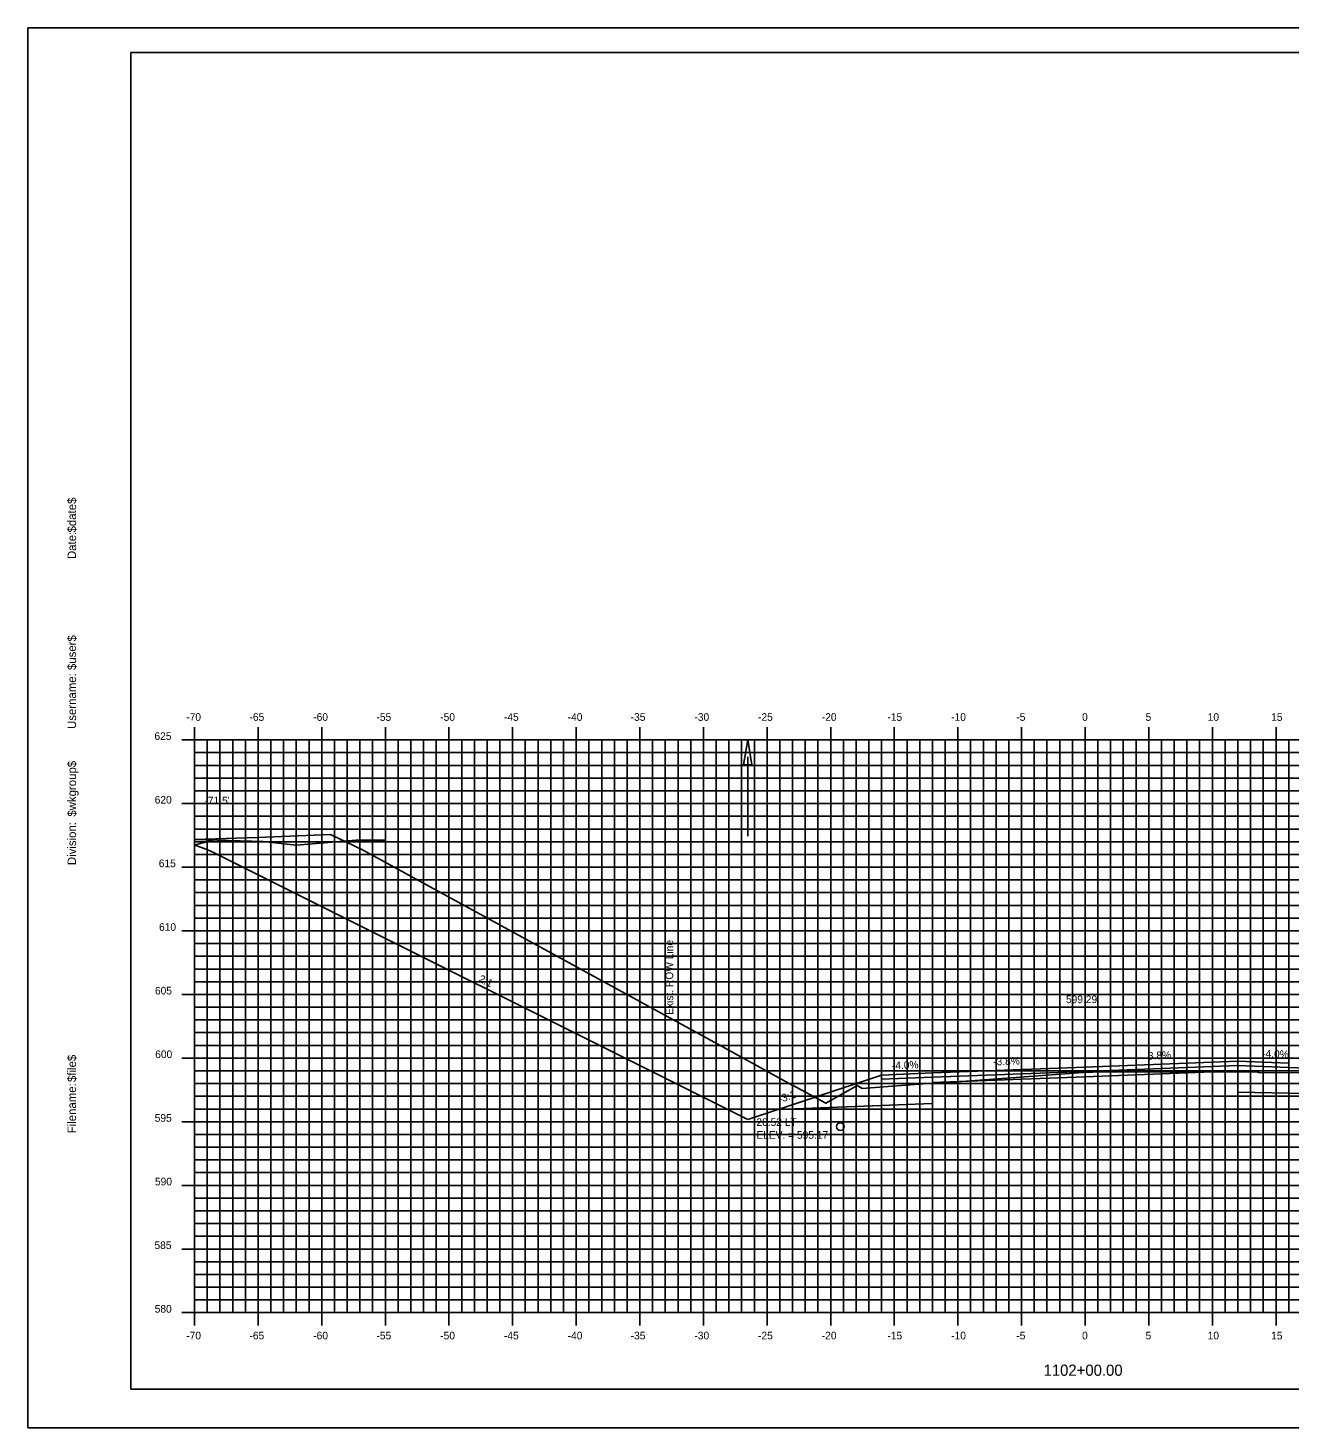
# Model space of a CAD drawing. Extents: x 1076969 to 1077139, y 779716 to 779826.
# Drawn here: x 1076969 to 1077068.1, y 779715.6 to 779825.6 of the extents above; entities that cross this region are included whole.
import ezdxf

# ---------------------------------------------------------------- set-up
doc = ezdxf.new("R2010")
doc.units = 0
for name, color, linetype in [('ANNOTATION', 7, 'Continuous'), ('BORDER', 7, 'Continuous'), ('D_Drainage_Ditch_Line', 7, 'Continuous'), ('D_Roadway_Centerline', 7, 'Continuous'), ('D_Roadway_Centerline_Text', 7, 'Continuous'), ('D_Roadway_Drive_Gravel_LT', 7, 'Continuous'), ('D_Roadway_Drive_SubGrade', 7, 'Continuous'), ('D_Roadway_Edge_Pavement', 7, 'Continuous'), ('D_Roadway_Edge_Shoulder', 7, 'Continuous'), ('D_Roadway_Pavement', 7, 'Continuous'), ('D_Roadway_SubGrade', 7, 'Continuous'), ('D_Text_Standard', 7, 'Continuous'), ('E_ROW_Line', 7, 'Continuous'), ('H_V ANNOTATION', 7, 'Continuous'), ('MAJOR', 7, 'Continuous'), ('MINOR', 7, 'Continuous'), ('PLOT BOUNDARY', 7, 'Continuous'), ('S_Drainage_Invert', 7, 'Continuous'), ('S_Roadway_Centerline', 7, 'Continuous')]:
    doc.layers.add(name, color=color, linetype=linetype)

msp = doc.modelspace()

# ---------------------------------------------------------------- linework, layer by layer
at = {"layer": 'BORDER'}
msp.add_lwpolyline([(1076977.06, 779718.71), (1077137.06, 779718.71), (1077137.06, 779823.71), (1076977.06, 779823.71)], close=True, dxfattribs=at)
at = {"layer": 'D_Drainage_Ditch_Line'}
msp.add_line((1077025.54, 779768.39), (1077025.54, 779762.15), dxfattribs=at)
msp.add_lwpolyline([(1077025.87, 779767.74), (1077025.21, 779767.74), (1077025.54, 779769.71)], close=True, dxfattribs=at)
at = {"layer": 'D_Roadway_Centerline'}
for points in [[(1076983.61, 779761.85), (1076982.61, 779761.6), (1076982.06, 779761.43)], [(1076982.06, 779761.43), (1076982.6, 779761.27), (1076983.29, 779761)]]:
    msp.add_lwpolyline(points, dxfattribs=at)
at = {"layer": 'D_Roadway_Drive_Gravel_LT'}
msp.add_line((1077025.54, 779739.88), (1077036.06, 779743.38), dxfattribs=at)
at = {"layer": 'D_Roadway_Drive_SubGrade'}
msp.add_lwpolyline([(1077025.54, 779739.88), (1076983.29, 779761)], dxfattribs=at)
at = {"layer": 'D_Roadway_Edge_Pavement'}
msp.add_lwpolyline([(1077040.06, 779743.21), (1077040.06, 779743.54), (1077052.06, 779744), (1077064.06, 779744.46), (1077064.06, 779744.12), (1077052.06, 779743.67)], close=True, dxfattribs=at)
at = {"layer": 'D_Roadway_Edge_Shoulder'}
msp.add_lwpolyline([(1077064.06, 779744.46), (1077068.06, 779744.3), (1077068.06, 779744.3)], dxfattribs=at)
msp.add_lwpolyline([(1077040.06, 779743.54), (1077036.06, 779743.38), (1077036.06, 779743.05), (1077040.06, 779743.21)], close=True, dxfattribs=at)
at = {"layer": 'D_Roadway_Pavement'}
msp.add_lwpolyline([(1077040.06, 779742.79), (1077040.06, 779743.21), (1077052.06, 779743.67), (1077064.06, 779744.12), (1077064.06, 779743.71), (1077052.06, 779743.25)], close=True, dxfattribs=at)
msp.add_lwpolyline([(1077040.06, 779743.21), (1077040.06, 779742.79)], dxfattribs=at)
msp.add_lwpolyline([(1077040.06, 779743.21), (1077040.06, 779742.79)], dxfattribs=at)
at = {"layer": 'D_Roadway_SubGrade'}
msp.add_line((1077036.06, 779740.98), (1077027.91, 779740.67), dxfattribs=at)
msp.add_lwpolyline([(1077064.06, 779742.04), (1077064.06, 779742.62), (1077064.06, 779744.12), (1077064.06, 779744.12), (1077070.06, 779743.88), (1077070.06, 779744.22), (1077080.05, 779741.72)], close=True, dxfattribs=at)
msp.add_lwpolyline([(1077027.91, 779740.67), (1077040.06, 779741.13), (1077040.06, 779743.54), (1077036.06, 779743.38), (1077036.06, 779743.05)], dxfattribs=at)
at = {"layer": 'E_ROW_Line'}
msp.add_line((1077020.08, 779747.51), (1077020.08, 779757.51), dxfattribs=at)
msp.add_line((1077020.08, 779747.51), (1077020.08, 779757.51), dxfattribs=at)
at = {"layer": 'MAJOR'}
for p, q in [((1076982.06, 779770.71), (1076982.06, 779769.71)), ((1076987.06, 779770.71), (1076987.06, 779769.71)), ((1076992.06, 779770.71), (1076992.06, 779769.71)), ((1076997.06, 779770.71), (1076997.06, 779769.71)), ((1077002.06, 779770.71), (1077002.06, 779769.71)), ((1077007.06, 779770.71), (1077007.06, 779769.71)), ((1077012.06, 779770.71), (1077012.06, 779769.71)), ((1077017.06, 779770.71), (1077017.06, 779769.71)), ((1077022.06, 779770.71), (1077022.06, 779769.71)), ((1077027.06, 779770.71), (1077027.06, 779769.71)), ((1077032.06, 779770.71), (1077032.06, 779769.71)), ((1077037.06, 779770.71), (1077037.06, 779769.71)), ((1077042.06, 779770.71), (1077042.06, 779769.71)), ((1077047.06, 779770.71), (1077047.06, 779769.71)), ((1077052.06, 779770.71), (1077052.06, 779769.71)), ((1077057.06, 779770.71), (1077057.06, 779769.71)), ((1077062.06, 779770.71), (1077062.06, 779769.71)), ((1077067.06, 779770.71), (1077067.06, 779769.71)), ((1076981.06, 779769.71), (1076982.06, 779769.71)), ((1076982.06, 779769.71), (1077122.06, 779769.71)), ((1076982.06, 779724.71), (1076982.06, 779769.71)), ((1076982.06, 779724.71), (1076982.06, 779769.71)), ((1076982.06, 779769.71), (1077122.06, 779769.71)), ((1076982.06, 779724.71), (1076982.06, 779769.71)), ((1076982.06, 779724.71), (1076982.06, 779769.71)), ((1076982.06, 779724.71), (1076982.06, 779769.71)), ((1076987.06, 779724.71), (1076987.06, 779769.71)), ((1076992.06, 779724.71), (1076992.06, 779769.71)), ((1076997.06, 779724.71), (1076997.06, 779769.71)), ((1077002.06, 779724.71), (1077002.06, 779769.71)), ((1077007.06, 779724.71), (1077007.06, 779769.71)), ((1077012.06, 779724.71), (1077012.06, 779769.71)), ((1077017.06, 779724.71), (1077017.06, 779769.71)), ((1077022.06, 779724.71), (1077022.06, 779769.71)), ((1077027.06, 779724.71), (1077027.06, 779769.71)), ((1077032.06, 779724.71), (1077032.06, 779769.71)), ((1077037.06, 779724.71), (1077037.06, 779769.71)), ((1077042.06, 779724.71), (1077042.06, 779769.71)), ((1077047.06, 779724.71), (1077047.06, 779769.71)), ((1077052.06, 779724.71), (1077052.06, 779769.71)), ((1077057.06, 779724.71), (1077057.06, 779769.71)), ((1077062.06, 779724.71), (1077062.06, 779769.71)), ((1077067.06, 779724.71), (1077067.06, 779769.71)), ((1076981.06, 779764.71), (1076982.06, 779764.71)), ((1076982.06, 779764.71), (1077122.06, 779764.71)), ((1076981.06, 779759.71), (1076982.06, 779759.71)), ((1076982.06, 779759.71), (1077122.06, 779759.71)), ((1076981.06, 779754.71), (1076982.06, 779754.71)), ((1076982.06, 779754.71), (1077122.06, 779754.71)), ((1076981.06, 779749.71), (1076982.06, 779749.71)), ((1076982.06, 779749.71), (1077122.06, 779749.71)), ((1076981.06, 779744.71), (1076982.06, 779744.71)), ((1076982.06, 779744.71), (1077122.06, 779744.71)), ((1076981.06, 779739.71), (1076982.06, 779739.71)), ((1076982.06, 779739.71), (1077122.06, 779739.71)), ((1076981.06, 779734.71), (1076982.06, 779734.71)), ((1076982.06, 779734.71), (1077122.06, 779734.71)), ((1076981.06, 779729.71), (1076982.06, 779729.71)), ((1076982.06, 779729.71), (1077122.06, 779729.71)), ((1076981.06, 779724.71), (1076982.06, 779724.71)), ((1076982.06, 779724.71), (1077122.06, 779724.71)), ((1076982.06, 779724.71), (1077122.06, 779724.71)), ((1076982.06, 779723.7), (1076982.06, 779724.71)), ((1076987.06, 779723.7), (1076987.06, 779724.71)), ((1076992.06, 779723.7), (1076992.06, 779724.71)), ((1076997.06, 779723.7), (1076997.06, 779724.71)), ((1077002.06, 779723.7), (1077002.06, 779724.71)), ((1077007.06, 779723.7), (1077007.06, 779724.71)), ((1077012.06, 779723.7), (1077012.06, 779724.71)), ((1077017.06, 779723.7), (1077017.06, 779724.71)), ((1077022.06, 779723.7), (1077022.06, 779724.71)), ((1077027.06, 779723.7), (1077027.06, 779724.71)), ((1077032.06, 779723.7), (1077032.06, 779724.71)), ((1077037.06, 779723.7), (1077037.06, 779724.71)), ((1077042.06, 779723.7), (1077042.06, 779724.71)), ((1077047.06, 779723.7), (1077047.06, 779724.71)), ((1077052.06, 779723.7), (1077052.06, 779724.71)), ((1077057.06, 779723.7), (1077057.06, 779724.71)), ((1077062.06, 779723.7), (1077062.06, 779724.71)), ((1077067.06, 779723.7), (1077067.06, 779724.71))]:
    msp.add_line(p, q, dxfattribs=at)
at = {"layer": 'MINOR'}
for p, q in [((1076983.06, 779724.71), (1076983.06, 779769.71)), ((1076984.06, 779724.71), (1076984.06, 779769.71)), ((1076985.06, 779724.71), (1076985.06, 779769.71)), ((1076986.06, 779724.71), (1076986.06, 779769.71)), ((1076988.06, 779724.71), (1076988.06, 779769.71)), ((1076989.06, 779724.71), (1076989.06, 779769.71)), ((1076990.06, 779724.71), (1076990.06, 779769.71)), ((1076991.06, 779724.71), (1076991.06, 779769.71)), ((1076993.06, 779724.71), (1076993.06, 779769.71)), ((1076994.06, 779724.71), (1076994.06, 779769.71)), ((1076995.06, 779724.71), (1076995.06, 779769.71)), ((1076996.06, 779724.71), (1076996.06, 779769.71)), ((1076998.06, 779724.71), (1076998.06, 779769.71)), ((1076999.06, 779724.71), (1076999.06, 779769.71)), ((1077000.06, 779724.71), (1077000.06, 779769.71)), ((1077001.06, 779724.71), (1077001.06, 779769.71)), ((1077003.06, 779724.71), (1077003.06, 779769.71)), ((1077004.06, 779724.71), (1077004.06, 779769.71)), ((1077005.06, 779724.71), (1077005.06, 779769.71)), ((1077006.06, 779724.71), (1077006.06, 779769.71)), ((1077008.06, 779724.71), (1077008.06, 779769.71)), ((1077009.06, 779724.71), (1077009.06, 779769.71)), ((1077010.06, 779724.71), (1077010.06, 779769.71)), ((1077011.06, 779724.71), (1077011.06, 779769.71)), ((1077013.06, 779724.71), (1077013.06, 779769.71)), ((1077014.06, 779724.71), (1077014.06, 779769.71)), ((1077015.06, 779724.71), (1077015.06, 779769.71)), ((1077016.06, 779724.71), (1077016.06, 779769.71)), ((1077018.06, 779724.71), (1077018.06, 779769.71)), ((1077019.06, 779724.71), (1077019.06, 779769.71)), ((1077020.06, 779724.71), (1077020.06, 779769.71)), ((1077021.06, 779724.71), (1077021.06, 779769.71)), ((1077023.06, 779724.71), (1077023.06, 779769.71)), ((1077024.06, 779724.71), (1077024.06, 779769.71)), ((1077025.06, 779724.71), (1077025.06, 779769.71)), ((1077026.06, 779724.71), (1077026.06, 779769.71)), ((1077028.06, 779724.71), (1077028.06, 779769.71)), ((1077029.06, 779724.71), (1077029.06, 779769.71)), ((1077030.06, 779724.71), (1077030.06, 779769.71)), ((1077031.06, 779724.71), (1077031.06, 779769.71)), ((1077033.06, 779724.71), (1077033.06, 779769.71)), ((1077034.06, 779724.71), (1077034.06, 779769.71)), ((1077035.06, 779724.71), (1077035.06, 779769.71)), ((1077036.06, 779724.71), (1077036.06, 779769.71)), ((1077038.06, 779724.71), (1077038.06, 779769.71)), ((1077039.06, 779724.71), (1077039.06, 779769.71)), ((1077040.06, 779724.71), (1077040.06, 779769.71)), ((1077041.06, 779724.71), (1077041.06, 779769.71)), ((1077043.06, 779724.71), (1077043.06, 779769.71)), ((1077044.06, 779724.71), (1077044.06, 779769.71)), ((1077045.06, 779724.71), (1077045.06, 779769.71)), ((1077046.06, 779724.71), (1077046.06, 779769.71)), ((1077048.06, 779724.71), (1077048.06, 779769.71)), ((1077049.06, 779724.71), (1077049.06, 779769.71)), ((1077050.06, 779724.71), (1077050.06, 779769.71)), ((1077051.06, 779724.71), (1077051.06, 779769.71)), ((1077053.06, 779724.71), (1077053.06, 779769.71)), ((1077054.06, 779724.71), (1077054.06, 779769.71)), ((1077055.06, 779724.71), (1077055.06, 779769.71)), ((1077056.06, 779724.71), (1077056.06, 779769.71)), ((1077058.06, 779724.71), (1077058.06, 779769.71)), ((1077059.06, 779724.71), (1077059.06, 779769.71)), ((1077060.06, 779724.71), (1077060.06, 779769.71)), ((1077061.06, 779724.71), (1077061.06, 779769.71)), ((1077063.06, 779724.71), (1077063.06, 779769.71)), ((1077064.06, 779724.71), (1077064.06, 779769.71)), ((1077065.06, 779724.71), (1077065.06, 779769.71)), ((1077066.06, 779724.71), (1077066.06, 779769.71)), ((1077068.06, 779724.71), (1077068.06, 779769.71)), ((1076982.06, 779768.71), (1077122.06, 779768.71)), ((1076982.06, 779768.71), (1076983.07, 779768.71)), ((1076982.06, 779767.71), (1077122.06, 779767.71)), ((1076982.06, 779767.71), (1076983.07, 779767.71)), ((1076982.06, 779766.71), (1077122.06, 779766.71)), ((1076982.06, 779766.71), (1076983.07, 779766.71)), ((1076982.06, 779765.71), (1077122.06, 779765.71)), ((1076982.06, 779765.71), (1076983.07, 779765.71)), ((1076982.06, 779763.71), (1077122.06, 779763.71)), ((1076982.06, 779763.71), (1076983.07, 779763.71)), ((1076982.06, 779762.71), (1077122.06, 779762.71)), ((1076982.06, 779762.71), (1076983.07, 779762.71)), ((1076982.06, 779761.71), (1077122.06, 779761.71)), ((1076982.06, 779761.71), (1076983.07, 779761.71)), ((1076982.06, 779760.71), (1077122.06, 779760.71)), ((1076982.06, 779760.71), (1076983.07, 779760.71)), ((1076982.06, 779758.71), (1077122.06, 779758.71)), ((1076982.06, 779758.71), (1076983.07, 779758.71)), ((1076982.06, 779757.71), (1077122.06, 779757.71)), ((1076982.06, 779757.71), (1076983.07, 779757.71)), ((1076982.06, 779756.71), (1077122.06, 779756.71)), ((1076982.06, 779756.71), (1076983.07, 779756.71)), ((1076982.06, 779755.71), (1077122.06, 779755.71)), ((1076982.06, 779755.71), (1076983.07, 779755.71)), ((1076982.06, 779753.71), (1077122.06, 779753.71)), ((1076982.06, 779753.71), (1076983.07, 779753.71)), ((1076982.06, 779752.71), (1077122.06, 779752.71)), ((1076982.06, 779752.71), (1076983.07, 779752.71)), ((1076982.06, 779751.71), (1077122.06, 779751.71)), ((1076982.06, 779751.71), (1076983.07, 779751.71)), ((1076982.06, 779750.71), (1077122.06, 779750.71)), ((1076982.06, 779750.71), (1076983.07, 779750.71)), ((1076982.06, 779748.71), (1077122.06, 779748.71)), ((1076982.06, 779748.71), (1076983.07, 779748.71)), ((1076982.06, 779747.71), (1077122.06, 779747.71)), ((1076982.06, 779747.71), (1076983.07, 779747.71)), ((1076982.06, 779746.71), (1077122.06, 779746.71)), ((1076982.06, 779746.71), (1076983.07, 779746.71)), ((1076982.06, 779745.71), (1077122.06, 779745.71)), ((1076982.06, 779745.71), (1076983.07, 779745.71)), ((1076982.06, 779743.71), (1077122.06, 779743.71)), ((1076982.06, 779743.71), (1076983.07, 779743.71)), ((1076982.06, 779742.71), (1077122.06, 779742.71)), ((1076982.06, 779742.71), (1076983.07, 779742.71)), ((1076982.06, 779741.71), (1077122.06, 779741.71)), ((1076982.06, 779741.71), (1076983.07, 779741.71)), ((1076982.06, 779740.71), (1077122.06, 779740.71)), ((1076982.06, 779740.71), (1076983.07, 779740.71)), ((1076982.06, 779738.71), (1077122.06, 779738.71)), ((1076982.06, 779738.71), (1076983.07, 779738.71)), ((1076982.06, 779737.71), (1077122.06, 779737.71)), ((1076982.06, 779737.71), (1076983.07, 779737.71)), ((1076982.06, 779736.71), (1077122.06, 779736.71)), ((1076982.06, 779736.71), (1076983.07, 779736.71)), ((1076982.06, 779735.71), (1077122.06, 779735.71)), ((1076982.06, 779735.71), (1076983.07, 779735.71)), ((1076982.06, 779733.71), (1077122.06, 779733.71)), ((1076982.06, 779733.71), (1076983.07, 779733.71)), ((1076982.06, 779732.71), (1077122.06, 779732.71)), ((1076982.06, 779732.71), (1076983.07, 779732.71)), ((1076982.06, 779731.71), (1077122.06, 779731.71)), ((1076982.06, 779731.71), (1076983.07, 779731.71)), ((1076982.06, 779730.71), (1077122.06, 779730.71)), ((1076982.06, 779730.71), (1076983.07, 779730.71)), ((1076982.06, 779728.71), (1077122.06, 779728.71)), ((1076982.06, 779728.71), (1076983.07, 779728.71)), ((1076982.06, 779727.71), (1077122.06, 779727.71)), ((1076982.06, 779727.71), (1076983.07, 779727.71)), ((1076982.06, 779726.71), (1077122.06, 779726.71)), ((1076982.06, 779726.71), (1076983.07, 779726.71)), ((1076982.06, 779725.71), (1077122.06, 779725.71)), ((1076982.06, 779725.71), (1076983.07, 779725.71))]:
    msp.add_line(p, q, dxfattribs=at)
at = {"layer": 'PLOT BOUNDARY'}
msp.add_lwpolyline([(1076968.97, 779715.65), (1077138.97, 779715.65), (1077138.97, 779825.65), (1076968.97, 779825.65)], close=True, dxfattribs=at)
at = {"layer": 'S_Drainage_Invert'}
msp.add_circle((1077032.81, 779739.33), 0.3, dxfattribs=at)
at = {"layer": 'S_Roadway_Centerline'}
for points in [[(1076982.06, 779761.89), (1076987, 779762.04), (1076992.74, 779762.29), (1076995.26, 779761.07), (1077023.76, 779745.5), (1077029.04, 779742.59), (1077029.11, 779742.56), (1077031.68, 779741.16), (1077034.02, 779742.49), (1077034.15, 779742.56), (1077034.54, 779742.32), (1077040.02, 779742.74), (1077040.34, 779742.78), (1077040.5, 779742.78), (1077040.51, 779742.73), (1077040.95, 779742.77), (1077052.24, 779743.6), (1077052.67, 779743.6), (1077065.11, 779743.62), (1077065.57, 779743.62), (1077065.76, 779743.55), (1077070.31, 779743.57)], [(1076982.06, 779761.89), (1076987, 779762.04), (1076992.74, 779762.29), (1076995.26, 779761.07), (1077023.76, 779745.5), (1077029.04, 779742.59), (1077029.11, 779742.56), (1077031.68, 779741.16), (1077034.02, 779742.49), (1077034.15, 779742.56), (1077034.54, 779742.32), (1077040.02, 779742.74), (1077040.34, 779742.78), (1077040.5, 779742.78), (1077040.51, 779742.73), (1077040.95, 779742.77), (1077052.24, 779743.6), (1077052.67, 779743.6), (1077065.11, 779743.62), (1077065.57, 779743.62), (1077065.76, 779743.55), (1077070.31, 779743.57)], [(1076997.06, 779761.83), (1076994.75, 779761.83), (1076990.06, 779761.43), (1076987.46, 779761.73), (1076982.06, 779761.89)]]:
    msp.add_lwpolyline(points, dxfattribs=at)

# ---------------------------------------------------------------- texts
at = {"layer": 'ANNOTATION'}
for s, rotation, p in [('2:1', 333.4349, (1077004.33, 779750.75)), ('3.8%', 2.1762, (1077057, 779744.59)), ('-4.0%', 357.7094, (1077065.96, 779744.78)), ('-4.0%', 2.2906, (1077036.88, 779743.82)), ('-3.8%', 2.1762, (1077044.84, 779744.13)), ('-3:1', 18.4349, (1077028.06, 779741.17))]:
    msp.add_text(s, height=0.6, rotation=rotation, dxfattribs=at).set_placement(p)
for s, p in [('26.52 LT', (1077026.22, 779739.38)), ('ELEV. = 595.17', (1077026.22, 779738.37))]:
    msp.add_text(s, height=0.6, dxfattribs=at).set_placement(p)
at = {"layer": 'BORDER'}
for s, p in [('$date$', (1076972.75, 779786.01)), ('Date:', (1076972.75, 779783.92)), ('$user$', (1076972.75, 779775.2)), ('Username:', (1076972.75, 779770.57)), ('$wkgroup$', (1076972.75, 779763.68)), ('Division:', (1076972.75, 779759.87)), ('$file$', (1076972.75, 779742.83)), ('Filename:', (1076972.75, 779738.8))]:
    msp.add_text(s, height=0.67, rotation=90, dxfattribs=at).set_placement(p)
at = {"layer": 'D_Roadway_Centerline_Text'}
msp.add_text('599.29', height=0.6, dxfattribs=at).set_placement((1077050.55, 779749.03))
at = {"layer": 'D_Text_Standard'}
msp.add_text("-71.5'", height=0.6, dxfattribs=at).set_placement((1076982.84, 779764.65))
at = {"layer": 'E_ROW_Line'}
msp.add_text('Exist. ROW Line', height=0.6, rotation=90, dxfattribs=at).set_placement((1077019.68, 779748.11))
at = {"layer": 'H_V ANNOTATION'}
for s, height, p in [('-70', 0.6, (1076981.41, 779771.21)), ('-65', 0.6, (1076986.38, 779771.21)), ('-60', 0.6, (1076991.39, 779771.21)), ('-55', 0.6, (1076996.36, 779771.21)), ('-50', 0.6, (1077001.37, 779771.21)), ('-45', 0.6, (1077006.38, 779771.21)), ('-40', 0.6, (1077011.39, 779771.21)), ('-35', 0.6, (1077016.34, 779771.21)), ('-30', 0.6, (1077021.35, 779771.21)), ('-25', 0.6, (1077026.35, 779771.21)), ('-20', 0.6, (1077031.36, 779771.21)), ('-15', 0.6, (1077036.52, 779771.21)), ('-10', 0.6, (1077041.53, 779771.21)), ('-5', 0.6, (1077046.65, 779771.21)), ('0', 0.6, (1077051.82, 779771.21)), ('5', 0.6, (1077056.81, 779771.21)), ('10', 0.6, (1077061.69, 779771.21)), ('15', 0.6, (1077066.68, 779771.21)), ('625', 0.6, (1076978.91, 779769.71)), ('620', 0.6, (1076978.93, 779764.71)), ('615', 0.6, (1076979.25, 779759.71)), ('610', 0.6, (1076979.27, 779754.71)), ('605', 0.6, (1076978.95, 779749.71)), ('600', 0.6, (1076978.97, 779744.71)), ('595', 0.6, (1076978.93, 779739.71)), ('590', 0.6, (1076978.95, 779734.71)), ('585', 0.6, (1076978.91, 779729.71)), ('580', 0.6, (1076978.93, 779724.71)), ('-70', 0.6, (1076981.41, 779722.61)), ('-65', 0.6, (1076986.38, 779722.61)), ('-60', 0.6, (1076991.39, 779722.61)), ('-55', 0.6, (1076996.36, 779722.61)), ('-50', 0.6, (1077001.37, 779722.61)), ('-45', 0.6, (1077006.38, 779722.61)), ('-40', 0.6, (1077011.39, 779722.61)), ('-35', 0.6, (1077016.34, 779722.61)), ('-30', 0.6, (1077021.35, 779722.61)), ('-25', 0.6, (1077026.35, 779722.61)), ('-20', 0.6, (1077031.36, 779722.61)), ('-15', 0.6, (1077036.52, 779722.61)), ('-10', 0.6, (1077041.53, 779722.61)), ('-5', 0.6, (1077046.65, 779722.61)), ('0', 0.6, (1077051.82, 779722.61)), ('5', 0.6, (1077056.81, 779722.61)), ('10', 0.6, (1077061.69, 779722.61)), ('15', 0.6, (1077066.68, 779722.61)), ('1102+00.00', 0.875, (1077048.79, 779719.75))]:
    msp.add_text(s, height=height, dxfattribs=at).set_placement(p)
at = {"layer": 'MAJOR'}
msp.add_text('-', height=0.006, dxfattribs=at).set_placement((1076982.06, 779724.71))

doc.saveas('drawing.dxf')
